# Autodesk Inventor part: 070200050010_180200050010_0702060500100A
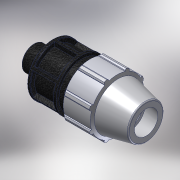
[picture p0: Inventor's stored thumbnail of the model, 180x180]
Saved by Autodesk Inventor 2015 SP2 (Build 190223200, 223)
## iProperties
Created: 2017-02
Part Number: 070200050010_180200050010_0702060500100A
Material: PVC-Piping
Description: PLASSON MALE ADAPTOR 50-1"
Document SubType Name: Modeling
Designer: KIM
Mass: 92.6774 g
Surface Area: 199.44 cm^2
Volume: 66.1981 cm^3
Density: 1.4 g/cm^3
Appearance: PTFE
Author: KIM
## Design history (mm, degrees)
derived "07020.ipt"
feature "Solid1::07020.ipt"
tag "TaggingFeature1"
body "Solid1"
other parameters: "d4" = 19, "d5" = 33.25, "d7" = 96, "d8" = 72, "d9" = 19, "d11" = 3.8, "d12" = 76.8, "d13" = 120 deg, "d14" = 75, "d15" = 8 deg, "d16" = 86.4, "d18" = 2.5, "d19" = 35 deg, "d20" = 17.5 deg, "d21" = 89.28, "d23" = 0, "d25" = 360 deg, "d27" = 1.92, "d34" = 4.8, "d36" = 0, "d42" = 33.25, "d43" = 2.88, "d46" = 1.5, "d49" = 106, "d51" = 133, "d53" = 1, "d55" = 360 deg, "d57" = 33.249, "d58" = 23.2743, "d59" = 26.6, "E_" = 96, "H_" = 133, "l_" = 106, "R_" = 33.249
